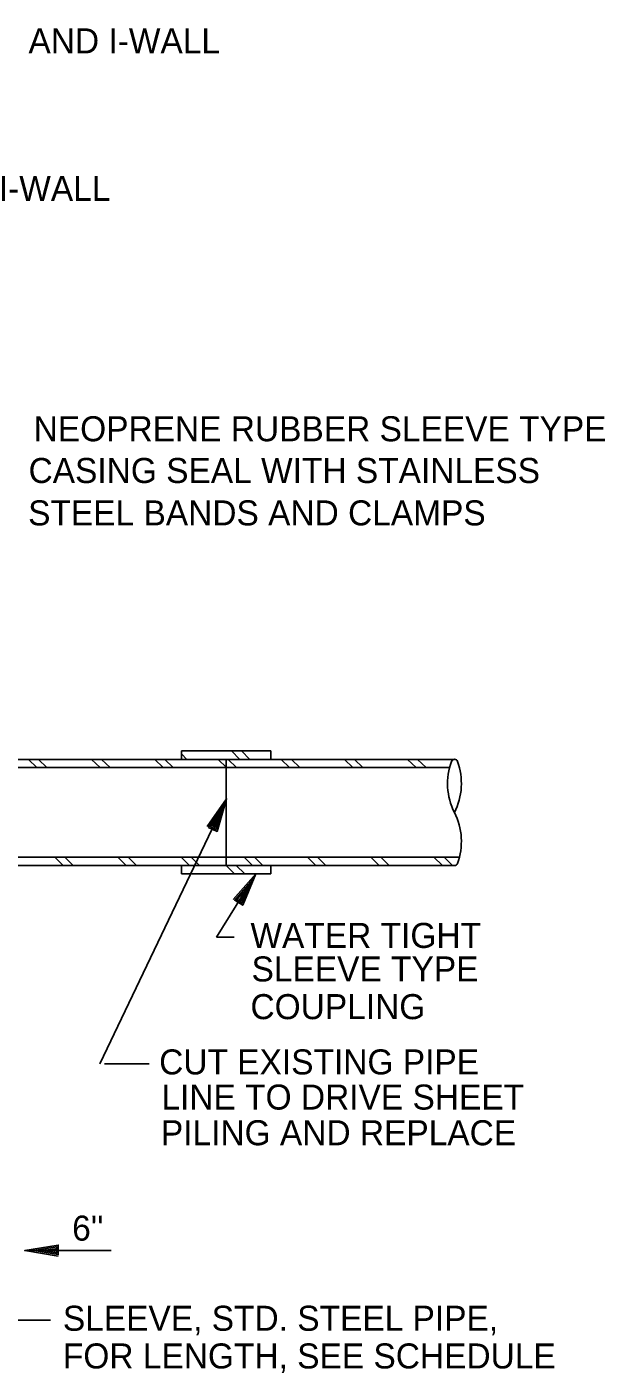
# Model space of a CAD drawing. Extents: x 22411.4 to 22495.4, y 22369.6 to 22415.
# Drawn here: x 22419.31 to 22423.62, y 22388.66 to 22398.7 of the extents above; entities that cross this region are included whole.
import ezdxf

# ---------------------------------------------------------------- set-up
doc = ezdxf.new("R2010")
doc.units = 0
for name, color, linetype in [('Level 1', 7, 'Continuous'), ('Level 2', 7, 'Continuous'), ('Level 4', 7, 'Continuous'), ('Level 8', 7, 'Continuous')]:
    doc.layers.add(name, color=color, linetype=linetype)

msp = doc.modelspace()

# ---------------------------------------------------------------- linework, layer by layer
at = {"layer": 'Level 1'}
for p, q in [((22420.765, 22392.882), (22420.765, 22392.882)), ((22420.795, 22392.945), (22420.795, 22392.945)), ((22421.012, 22392.385), (22421.012, 22392.385)), ((22420.975, 22392.326), (22420.975, 22392.326)), ((22419.934, 22389.577), (22419.289, 22389.577))]:
    msp.add_line(p, q, dxfattribs=at)
for points in [[(22420.498, 22393.239), (22420.458, 22393.279)], [(22420.894, 22393.239), (22420.831, 22393.302)], [(22420.969, 22393.239), (22420.907, 22393.302)], [(22419.379, 22393.177), (22419.317, 22393.239)], [(22419.455, 22393.177), (22419.392, 22393.239)], [(22419.851, 22393.177), (22419.788, 22393.239)], [(22419.926, 22393.177), (22419.863, 22393.239)], [(22420.322, 22393.177), (22420.259, 22393.239)], [(22420.397, 22393.177), (22420.335, 22393.239)], [(22420.793, 22393.177), (22420.731, 22393.239)], [(22420.869, 22393.177), (22420.806, 22393.239)], [(22421.265, 22393.177), (22421.202, 22393.239)], [(22421.34, 22393.177), (22421.278, 22393.239)], [(22421.736, 22393.177), (22421.674, 22393.239)], [(22421.812, 22393.177), (22421.749, 22393.239)], [(22422.208, 22393.177), (22422.145, 22393.239)], [(22422.283, 22393.177), (22422.22, 22393.239)], [(22419.575, 22392.447), (22419.513, 22392.51)], [(22419.651, 22392.447), (22419.588, 22392.51)], [(22420.047, 22392.447), (22419.984, 22392.51)], [(22420.122, 22392.447), (22420.06, 22392.51)], [(22420.518, 22392.447), (22420.456, 22392.51)], [(22420.593, 22392.447), (22420.531, 22392.51)], [(22420.989, 22392.447), (22420.927, 22392.51)], [(22421.065, 22392.447), (22421.002, 22392.51)], [(22421.461, 22392.447), (22421.398, 22392.51)], [(22421.536, 22392.447), (22421.474, 22392.51)], [(22421.932, 22392.447), (22421.87, 22392.51)], [(22422.008, 22392.447), (22421.945, 22392.51)], [(22422.404, 22392.447), (22422.341, 22392.51)], [(22422.479, 22392.447), (22422.417, 22392.51)], [(22420.459, 22392.385), (22420.458, 22392.386)], [(22420.855, 22392.385), (22420.792, 22392.447)], [(22420.93, 22392.385), (22420.867, 22392.447)]]:
    msp.add_lwpolyline(points, dxfattribs=at)
for centre, radius, start, end in [((22422.923, 22393.058), 0.48, 159.8064, 206.6071), ((22422.495, 22393.216), 0.0235, 20.1936, 159.8064), ((22422.066, 22393.058), 0.48, 333.3929, 20.1936), ((22422.066, 22392.628), 0.48, 339.8081, 26.6071), ((22422.495, 22392.471), 0.0235, 270, 339.6845)]:
    msp.add_arc(centre, radius, start, end, dxfattribs=at)
at = {"layer": 'Level 2'}
for p, q in [((22420.458, 22393.239), (22420.458, 22393.302)), ((22420.458, 22393.302), (22421.125, 22393.302)), ((22421.125, 22393.239), (22421.125, 22393.302)), ((22417.291, 22393.239), (22422.495, 22393.239)), ((22417.291, 22393.177), (22422.456, 22393.177)), ((22420.791, 22392.447), (22420.791, 22393.239)), ((22419.849, 22390.969), (22420.795, 22392.945)), ((22417.291, 22392.51), (22422.531, 22392.51)), ((22417.291, 22392.447), (22422.495, 22392.447)), ((22420.458, 22392.385), (22420.458, 22392.447)), ((22420.458, 22392.385), (22421.125, 22392.385)), ((22421.012, 22392.385), (22420.719, 22391.913)), ((22421.125, 22392.385), (22421.125, 22392.447)), ((22420.719, 22391.913), (22420.851, 22391.913)), ((22419.885, 22390.969), (22420.218, 22390.969))]:
    msp.add_line(p, q, dxfattribs=at)
for points in [[(22420.65, 22392.738), (22420.795, 22392.945), (22420.724, 22392.702), (22420.66, 22392.732), (22420.765, 22392.882), (22420.717, 22392.717), (22420.676, 22392.737), (22420.736, 22392.822), (22420.709, 22392.733), (22420.693, 22392.741), (22420.706, 22392.76)], [(22420.845, 22392.195), (22421.012, 22392.385), (22420.916, 22392.151), (22420.856, 22392.188), (22420.975, 22392.326), (22420.91, 22392.167), (22420.871, 22392.191), (22420.94, 22392.269), (22420.904, 22392.183), (22420.888, 22392.193), (22420.904, 22392.21)], [(22419.481, 22389.059), (22419.236, 22389.059), (22418.059, 22391.718)], [(22419.539, 22389.535), (22419.289, 22389.577), (22419.539, 22389.618), (22419.539, 22389.547), (22419.359, 22389.577), (22419.528, 22389.605), (22419.528, 22389.559), (22419.425, 22389.577), (22419.517, 22389.591), (22419.517, 22389.573), (22419.495, 22389.577)]]:
    msp.add_lwpolyline(points, dxfattribs=at)
at = {"layer": 'Level 8'}
msp.add_line((22419.359, 22389.577), (22419.359, 22389.577), dxfattribs=at)

# ---------------------------------------------------------------- texts
at = {"layer": 'Level 4'}
for s, height, p in [('C/L SHEET PILING AND I-WALL', 0.18667, (22417.07, 22398.502)), ('I-WALL', 0.1867, (22419.096, 22397.402)), ('NEOPRENE RUBBER SLEEVE TYPE', 0.18667, (22419.356, 22395.61)), ('CASING SEAL WITH STAINLESS', 0.18667, (22419.318, 22395.299)), ('STEEL BANDS AND CLAMPS', 0.18667, (22419.315, 22394.983)), ('WATER TIGHT', 0.18667, (22420.973, 22391.833)), ('SLEEVE TYPE', 0.18667, (22420.981, 22391.583)), ('COUPLING', 0.1867, (22420.973, 22391.302)), ('CUT EXISTING PIPE', 0.18667, (22420.292, 22390.89)), ('LINE TO DRIVE SHEET', 0.18667, (22420.309, 22390.628)), ('PILING AND REPLACE', 0.18667, (22420.305, 22390.362)), ("6''", 0.1867, (22419.643, 22389.651)), ('SLEEVE, STD. STEEL PIPE,', 0.18667, (22419.574, 22388.979)), ('FOR LENGTH, SEE SCHEDULE', 0.18667, (22419.574, 22388.698))]:
    msp.add_text(s, height=height, dxfattribs=at).set_placement(p)

doc.saveas('drawing.dxf')
